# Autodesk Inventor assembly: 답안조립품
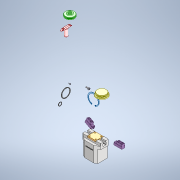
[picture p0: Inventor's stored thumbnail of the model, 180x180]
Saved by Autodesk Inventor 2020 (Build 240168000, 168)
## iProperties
Created: 2023-05
Part Number: 답안조립품
Document SubType Name: Assembly
Designer: oem
Author: oem
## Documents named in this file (12)
- C:\Users\oem\Desktop\730506V1011\답안조립품.iam
- C:\Users\oem\Desktop\730506V1011\본체.ipt
- C:\Users\oem\Desktop\730506V1011\C형 구멍용 멈춤링 60x2.ipt
- C:\Users\oem\Desktop\730506V1011\O링 P16.ipt
- C:\Users\oem\Desktop\730506V1011\O링 P44.ipt
- C:\Users\oem\Desktop\730506V1011\볼트 M3 x 6.ipt
- C:\Users\oem\Desktop\730506V1011\볼트 M6 x 12.ipt
- C:\Users\oem\Desktop\730506V1011\앤드캡.ipt
- C:\Users\oem\Desktop\730506V1011\척.ipt
- C:\Users\oem\Desktop\730506V1011\커버.ipt
- C:\Users\oem\Desktop\730506V1011\피스톤 로드.ipt
- C:\Users\oem\Desktop\730506V1011\피스톤.ipt
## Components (5 placed, 5 different names)
1. C형 구멍용 멈춤링 60x2:1
2. O링 P16:1
3. O링 P44:1
4. 피스톤 로드:1
5. 피스톤:1
